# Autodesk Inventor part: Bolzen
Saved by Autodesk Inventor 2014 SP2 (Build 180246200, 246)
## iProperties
Created: 2015-07
Part Number: Bolzen
Material: Generisch
Document SubType Name: Modeling
Designer: e_krauts
Density: 1 g/cm^3
Appearance: Vorgabe
Mass: 8.31069 g
Surface Area: 31.7053 cm^2
Volume: 8.31069 cm^3
Sending System: SolidWorks 2011
Last Author: e_boekem
Erstellt durch: XYZ
Werkstoff: AlCu4PbMg
Einheit: Stck.
UNIT_OF_MEASURE: Sachnummer
Author: e_krauts
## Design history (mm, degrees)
node "Bolzen.ipt1"
node "Stirnsenkung für M8 Zylinderschraube mit Innensechskant1"
node "Basis1"
